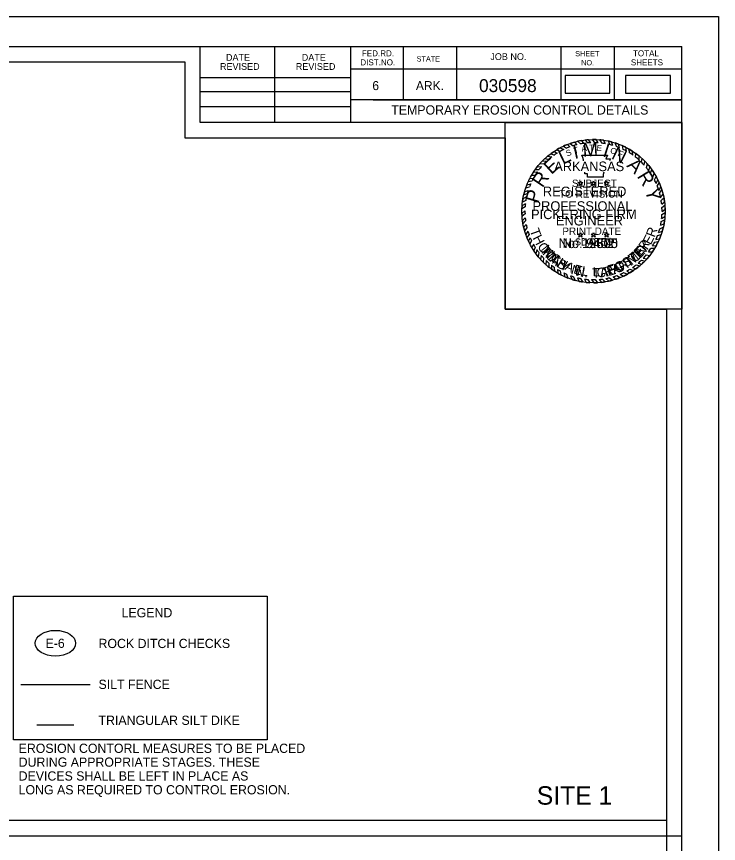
# Model space of a CAD drawing. Extents: x 814841 to 962585, y -174183 to 1802800.
# Drawn here: x 818181 to 818638, y 1802262 to 1802800 of the extents above; entities that cross this region are included whole.
import ezdxf

# ---------------------------------------------------------------- set-up
doc = ezdxf.new("R2010")
doc.units = 0
for name, color, linetype in [('_Silt Dike Legend', 7, 'Continuous'), ('Default', 7, 'Continuous'), ('Legend', 7, 'Continuous'), ('R_Border', 7, 'Continuous'), ('R_Border Notes', 7, 'Continuous'), ('R_Border Plan-Plan', 7, 'Continuous'), ('R_No Plot', 7, 'Continuous'), ('STAMP_PE_CRAFTON', 7, 'Continuous'), ('STAMP_PE_FOSTER', 7, 'Continuous'), ('STAMP_PE_SEAL-INFO', 7, 'Continuous'), ('STAMP_PE_TAEGTMEYER', 7, 'Continuous'), ('STAMP_PE_TXT', 7, 'Continuous'), ('STAMP_PRELIMINARY', 7, 'Continuous'), ('Veg Buffer', 7, 'Continuous')]:
    doc.layers.add(name, color=color, linetype=linetype)

# ---------------------------------------------------------------- blocks, each defined once
blk = doc.blocks.new('E-6')
at = {"layer": 'Default'}
blk.add_ellipse((0, 0), major_axis=(13.15, 0), ratio=0.638788, dxfattribs=at)
blk.add_text('E-6', height=6, dxfattribs=at).set_placement((-6.43, -3))

msp = doc.modelspace()

# ---------------------------------------------------------------- linework, layer by layer
at = {"layer": '_Silt Dike Legend'}
msp.add_line((818194.5, 1802339.12), (818218.5, 1802339.12), dxfattribs=at)
at = {"layer": 'Legend'}
msp.add_line((818184.07, 1802365.5), (818229.09, 1802365.5), dxfattribs=at)
msp.add_lwpolyline([(818179.3, 1802422.91), (818344.3, 1802422.91), (818344.3, 1802329.38), (818179.3, 1802329.38)], close=True, dxfattribs=at)
at = {"layer": 'R_Border'}
for p, q in [((817033.1, 1802780.6), (818614, 1802780.6)), ((818300.8, 1802731.2), (818300.8, 1802780.6)), ((818349.2, 1802731.2), (818349.2, 1802780.6)), ((818398.5, 1802780.6), (818398.5, 1802731.2)), ((818432.7, 1802780.6), (818432.7, 1802745.9)), ((818467.4, 1802780.6), (818467.4, 1802745.9)), ((818535.3, 1802780.6), (818535.3, 1802745.9)), ((818570, 1802780.6), (818570, 1802745.9)), ((818614, 1801753.3), (818614, 1802780.6)), ((818614, 1802765.9), (818398.5, 1802765.9)), ((818614, 1802766), (818614, 1802766)), ((818300.8, 1802760.5), (818398.5, 1802760.5)), ((818300.8, 1802751.2), (818398.5, 1802751.2)), ((818614, 1802745.9), (818398.5, 1802745.9)), ((818413.3, 1802745.9), (818614, 1802745.9)), ((818300.8, 1802741.5), (818398.5, 1802741.5)), ((818614, 1802731.2), (818300.8, 1802731.2))]:
    msp.add_line(p, q, dxfattribs=at)
at = {"layer": 'R_Border Plan-Plan'}
msp.add_line((817033.1, 1802266.95), (818614, 1802266.95), dxfattribs=at)
at = {"layer": 'R_No Plot'}
for points in [[(816971.06, 1802800.08), (818637.76, 1802800.08), (818637.76, 1801733.39), (816971.06, 1801733.39)], [(818604, 1802276.95), (817043.1, 1802276.95), (817043.1, 1802770.6), (818290.8, 1802770.6), (818290.8, 1802721.2), (818378.5, 1802721.2), (818499, 1802721.2), (818499, 1802609.54), (818604, 1802609.54)], [(818604, 1802276.95), (817043.1, 1802276.95), (817043.1, 1802770.6), (818290.8, 1802770.6), (818290.8, 1802721.2), (818378.5, 1802721.2), (818499, 1802721.2), (818499, 1802609.54), (818604, 1802609.54)], [(818604, 1802276.95), (817043.1, 1802276.95), (817043.1, 1802770.6), (818290.8, 1802770.6), (818290.8, 1802721.2), (818378.5, 1802721.2), (818499, 1802721.2), (818499, 1802609.54), (818604, 1802609.54)], [(818604, 1802276.95), (817043.1, 1802276.95), (817043.1, 1802770.6), (818290.8, 1802770.6), (818290.8, 1802721.2), (818378.5, 1802721.2), (818499, 1802721.2), (818499, 1802609.54), (818604, 1802609.54)], [(818604, 1802276.95), (817043.1, 1802276.95), (817043.1, 1802770.6), (818290.8, 1802770.6), (818290.8, 1802721.2), (818378.5, 1802721.2), (818499, 1802721.2), (818499, 1802609.54), (818604, 1802609.54)], [(818604, 1802276.95), (817043.1, 1802276.95), (817043.1, 1802770.6), (818290.8, 1802770.6), (818290.8, 1802721.2), (818378.5, 1802721.2), (818499, 1802721.2), (818499, 1802609.54), (818604, 1802609.54)], [(817043.1, 1802770.6), (818290.8, 1802770.6), (818290.8, 1802721.2), (818378.5, 1802721.2), (818499, 1802721.2), (818499, 1802609.54), (818604, 1802609.54), (818604, 1801763.3), (817043.1, 1801763.3)], [(818604, 1802276.95), (817043.1, 1802276.95), (817043.1, 1802770.6), (818290.8, 1802770.6), (818290.8, 1802721.2), (818378.5, 1802721.2), (818499, 1802721.2), (818499, 1802609.54), (818604, 1802609.54)], [(818499, 1802731.2), (818614, 1802731.2), (818614, 1802609.54), (818499, 1802609.54)]]:
    msp.add_lwpolyline(points, close=True, dxfattribs=at)
at = {"layer": 'STAMP_PE_SEAL-INFO'}
for p, q in [((818546.19, 1802718.88), (818547.97, 1802717.16)), ((818548.6, 1802719.36), (818550.1, 1802717.52)), ((818551.18, 1802719.72), (818552.59, 1802717.81)), ((818554.86, 1802717.95), (818553.3, 1802719.92)), ((818557.35, 1802717.98), (818555.95, 1802720.03)), ((818559.64, 1802717.87), (818558.35, 1802719.99)), ((818562.17, 1802717.62), (818560.71, 1802719.84)), ((818564.29, 1802717.3), (818563.01, 1802719.57)), ((818567.11, 1802716.7), (818566.24, 1802719)), ((818569.11, 1802716.16), (818568.32, 1802718.51)), ((818532.62, 1802713.45), (818534.79, 1802712.34)), ((818534.86, 1802714.7), (818537.18, 1802713.58)), ((818537.02, 1802715.76), (818538.97, 1802714.39)), ((818539.56, 1802716.84), (818541.03, 1802715.21)), ((818541.3, 1802717.48), (818543.2, 1802715.95)), ((818544.25, 1802718.39), (818545.69, 1802716.65)), ((818571.37, 1802715.43), (818570.67, 1802717.82)), ((818573.46, 1802714.63), (818572.74, 1802717.11)), ((818575.77, 1802713.6), (818575.26, 1802716.09)), ((818578, 1802712.45), (818577.57, 1802715)), ((818579.94, 1802711.32), (818579.74, 1802713.82)), ((818524.99, 1802707.76), (818527.28, 1802707.07)), ((818526.7, 1802709.26), (818529.35, 1802708.76)), ((818528.59, 1802710.9), (818530.87, 1802709.87)), ((818530.69, 1802712.23), (818532.9, 1802711.22)), ((818548.86, 1802709.87), (818565.58, 1802709.87)), ((818549.47, 1802708.34), (818548.86, 1802709.87)), ((818549.99, 1802706.85), (818549.47, 1802708.34)), ((818565.58, 1802709.87), (818564.46, 1802707.41)), ((818582.11, 1802709.89), (818581.96, 1802712.46)), ((818583.91, 1802708.55), (818584.08, 1802710.99)), ((818586.15, 1802706.69), (818586.24, 1802709.31)), ((818587.71, 1802705.23), (818588.06, 1802707.72)), ((818519.97, 1802702.37), (818522.71, 1802702.48)), ((818521.69, 1802704.42), (818524.3, 1802704.23)), ((818523.31, 1802706.14), (818526.03, 1802705.94)), ((818550.03, 1802706.28), (818549.99, 1802706.85)), ((818564.46, 1802707.41), (818567.62, 1802707.41)), ((818567.62, 1802707.41), (818566.9, 1802706.28)), ((818589.5, 1802703.36), (818589.84, 1802705.99)), ((818590.87, 1802701.78), (818591.56, 1802704.14)), ((818516.17, 1802696.79), (818518.62, 1802696.89)), ((818517.4, 1802698.8), (818519.98, 1802698.97)), ((818518.58, 1802700.52), (818521.1, 1802700.49)), ((818550.98, 1802697.73), (818550.85, 1802698.82)), ((818552.55, 1802697.73), (818550.98, 1802697.73)), ((818552.55, 1802695.58), (818552.55, 1802697.73)), ((818562.78, 1802697.27), (818562.7, 1802695.58)), ((818563.17, 1802698.82), (818562.78, 1802697.27)), ((818592.49, 1802699.7), (818593.17, 1802702.19)), ((818593.59, 1802698.12), (818594.48, 1802700.44)), ((818595.13, 1802695.63), (818596.05, 1802698.09)), ((818514.08, 1802692.73), (818516.59, 1802693.25)), ((818515.02, 1802694.68), (818517.51, 1802695)), ((818562.7, 1802695.58), (818552.55, 1802695.58)), ((818596.13, 1802693.8), (818597.26, 1802696.02)), ((818597.29, 1802691.38), (818598.42, 1802693.81)), ((818597.99, 1802689.7), (818599.31, 1802691.86)), ((818511.62, 1802686.02), (818514.01, 1802686.87)), ((818512.41, 1802688.54), (818514.83, 1802689.22)), ((818513.16, 1802690.57), (818515.68, 1802691.3)), ((818598.96, 1802686.95), (818600.31, 1802689.32)), ((818599.5, 1802685.13), (818600.97, 1802687.39)), ((818512.92, 1802682.75), (818510.59, 1802681.51)), ((818511.1, 1802683.99), (818513.45, 1802684.95)), ((818600.17, 1802682.33), (818601.76, 1802684.57)), ((818600.51, 1802680.43), (818602.28, 1802682.2)), ((818512.02, 1802676.16), (818509.91, 1802674.87)), ((818512.2, 1802678.28), (818510.01, 1802676.88)), ((818512.49, 1802680.46), (818510.27, 1802679.35)), ((818600.84, 1802677.89), (818602.71, 1802679.57)), ((818601, 1802675.8), (818602.95, 1802677.26)), ((818511.93, 1802673.69), (818509.91, 1802672.01)), ((818511.97, 1802671.66), (818510.01, 1802670.03)), ((818601.01, 1802671.18), (818603.11, 1802672.57)), ((818601.07, 1802673.21), (818603.09, 1802674.82)), ((818512.13, 1802669.18), (818510.28, 1802667.4)), ((818512.39, 1802667.03), (818510.62, 1802665.17)), ((818512.78, 1802664.74), (818511.09, 1802662.9)), ((818600.11, 1802664.21), (818602.38, 1802665.19)), ((818600.56, 1802666.71), (818602.77, 1802667.81)), ((818600.81, 1802668.65), (818602.98, 1802669.93)), ((818513.25, 1802662.64), (818511.69, 1802660.57)), ((818513.87, 1802660.41), (818512.4, 1802658.32)), ((818598.83, 1802659.48), (818601.28, 1802660.48)), ((818599.57, 1802661.95), (818601.92, 1802662.96)), ((818514.58, 1802658.29), (818513.17, 1802656.23)), ((818515.41, 1802656.16), (818514.1, 1802654.05)), ((818516.27, 1802654.24), (818515.13, 1802651.94)), ((818597.09, 1802655.01), (818599.53, 1802655.49)), ((818598.16, 1802657.58), (818600.57, 1802658.23)), ((818517.44, 1802651.95), (818516.49, 1802649.5)), ((818518.62, 1802649.93), (818517.7, 1802647.58)), ((818594.06, 1802649.43), (818596.45, 1802649.4)), ((818594.92, 1802650.83), (818597.43, 1802651.1)), ((818596.28, 1802653.33), (818598.72, 1802653.67)), ((818519.63, 1802648.38), (818519.08, 1802645.62)), ((818521.04, 1802646.42), (818520.53, 1802643.77)), ((818522.56, 1802644.54), (818522.12, 1802641.94)), ((818590.83, 1802644.99), (818593.13, 1802644.59)), ((818592.36, 1802646.96), (818594.89, 1802646.97)), ((818524.07, 1802642.85), (818523.76, 1802640.24)), ((818525.68, 1802641.22), (818525.53, 1802638.58)), ((818527.4, 1802639.66), (818527.39, 1802637.01)), ((818529.2, 1802638.19), (818529.3, 1802635.56)), ((818584.25, 1802638.54), (818586.59, 1802637.82)), ((818585.61, 1802639.67), (818587.96, 1802639.02)), ((818587.64, 1802641.53), (818589.84, 1802640.84)), ((818588.91, 1802642.82), (818591.29, 1802642.4)), ((818530.89, 1802636.94), (818531.07, 1802634.35)), ((818533.03, 1802635.53), (818533.33, 1802632.97)), ((818534.78, 1802634.5), (818535.24, 1802631.93)), ((818537.19, 1802633.25), (818537.97, 1802630.64)), ((818539.05, 1802632.41), (818539.91, 1802629.85)), ((818573.82, 1802632.35), (818575.94, 1802631.05)), ((818576.12, 1802633.4), (818578.54, 1802632.34)), ((818578.16, 1802634.47), (818580.24, 1802633.3)), ((818580.23, 1802635.69), (818582.48, 1802634.71)), ((818581.95, 1802636.83), (818584.14, 1802635.88)), ((818541.51, 1802631.44), (818542.56, 1802628.94)), ((818543.56, 1802630.77), (818544.69, 1802628.32)), ((818546.1, 1802630.08), (818547.16, 1802627.75)), ((818548.09, 1802629.65), (818549.32, 1802627.36)), ((818550.59, 1802629.24), (818551.79, 1802627.04)), ((818552.77, 1802629), (818554.14, 1802626.86)), ((818555.19, 1802628.87), (818556.71, 1802626.8)), ((818557.49, 1802628.86), (818559.21, 1802626.88)), ((818560.09, 1802628.99), (818561.71, 1802627.09)), ((818562.28, 1802629.22), (818564.14, 1802627.43)), ((818564.5, 1802629.57), (818566.45, 1802627.88)), ((818566.97, 1802630.09), (818568.85, 1802628.47)), ((818569.26, 1802630.72), (818571.34, 1802629.23)), ((818571.73, 1802631.53), (818573.94, 1802630.19))]:
    msp.add_line(p, q, dxfattribs=at)
for radius, start, end in [(46.61, 99.7525, 102.7765), (46.61, 93.9381, 96.5517), (46.61, 87.7298, 90.6707), (46.61, 81.9732, 84.8236), (46.61, 75.3125, 77.9426), (46.61, 117.6544, 120.8099), (44.57, 115.6869, 119.1583), (46.61, 111.3124, 114.7026), (44.57, 110.3086, 113.1659), (46.61, 105.2339, 109.0352), (44.57, 104.0352, 107.3615), (44.57, 98.258, 101.0329), (44.57, 92.1102, 95.0367), (44.57, 85.9628, 88.9097), (44.57, 79.9264, 82.696), (44.57, 73.5575, 76.2314), (46.61, 69.6061, 72.3058), (44.57, 67.6248, 70.504), (46.61, 63.1329, 66.2704), (44.57, 61.1558, 64.3784), (46.61, 56.9003, 60.0942), (46.61, 129.7326, 132.5376), (44.57, 127.5297, 130.9683), (46.61, 123.6199, 126.5906), (44.57, 121.9746, 125.11), (44.57, 54.9238, 58.2702), (44.57, 48.3016, 52.0395), (46.61, 50.3492, 53.7159), (46.61, 44.3405, 47.3929), (46.61, 141.6056, 144.4486), (44.57, 139.301, 142.5873), (46.61, 135.4021, 138.3031), (44.57, 133.1331, 136.2562), (44.57, 42.2212, 45.5512), (46.61, 38.1247, 41.2316), (46.61, 147.0072, 149.899), (44.57, 145.0197, 148.2104), (44.57, 36.135, 39.5311), (44.57, 29.9032, 33.6645), (46.61, 31.9614, 35.4294), (46.61, 152.864, 155.5189), (44.57, 151.0315, 153.573), (44.57, 23.7732, 27.2211), (46.61, 25.9391, 29.0125), (46.61, 19.9538, 23.3141), (46.61, 158.4077, 161.0701), (44.57, 162.4331, 165.0013), (44.57, 156.3402, 159.2319), (44.57, 17.6802, 21.4251), (46.61, 13.8421, 17.4447), (46.61, 170.0003, 172.6878), (46.61, 164.3068, 166.894), (44.57, 167.9048, 170.9039), (44.57, 11.5444, 15.2364), (46.61, 7.5852, 10.8621), (46.61, 175.7409, 178.2066), (44.57, 173.73, 176.4734), (44.57, 5.7599, 9.0606), (44.57, 359.7329, 3.0639), (46.61, 1.7215, 4.7268), (46.61, 181.7251, 184.1626), (44.57, 179.6454, 182.2633), (44.57, 353.8632, 357.1274), (46.61, 355.7156, 358.9569), (46.61, 187.4204, 190.1927), (44.57, 185.4539, 188.234), (44.57, 191.2274, 193.9858), (44.57, 348.0778, 351.3435), (46.61, 349.8305, 353.0885), (46.61, 193.0369, 195.9973), (44.57, 196.9675, 199.8353), (44.57, 341.777, 345.0925), (46.61, 343.8925, 347.035), (46.61, 198.8967, 201.6281), (46.61, 204.5479, 207.4328), (44.57, 202.7761, 205.4791), (44.57, 335.6038, 339.1858), (46.61, 337.3837, 340.9933), (46.61, 210.8636, 213.6571), (44.57, 208.7883, 211.7934), (44.57, 323.5851, 327.4407), (46.61, 325.4405, 328.9872), (44.57, 329.5549, 333.2076), (46.61, 331.4037, 334.9332), (46.61, 216.6115, 219.491), (44.57, 214.1838, 217.2747), (44.57, 220.3909, 223.3056), (44.57, 316.6531, 320.3711), (46.61, 318.2846, 321.8043), (46.61, 222.48, 225.3801), (46.61, 228.3665, 231.348), (44.57, 226.2494, 229.2407), (44.57, 232.229, 234.9336), (44.57, 304.823, 308.5143), (46.61, 306.3721, 310.208), (44.57, 310.7744, 314.3161), (46.61, 312.4518, 315.6633), (46.61, 234.295, 236.9452), (44.57, 238.2223, 240.8353), (46.61, 240.1977, 242.8613), (44.57, 244.3204, 246.9486), (44.57, 292.8745, 296.1185), (46.61, 294.6481, 298.2166), (44.57, 299.0768, 302.1724), (46.61, 300.621, 303.8703), (46.61, 246.576, 249.1558), (44.57, 250.3491, 253.1216), (46.61, 252.5967, 255.3252), (44.57, 256.505, 259.1192), (46.61, 258.4433, 261.1398), (44.57, 262.3783, 265.2012), (46.61, 264.1978, 267.1009), (44.57, 268.3215, 271.277), (44.57, 274.6157, 277.4486), (46.61, 276.4239, 279.4357), (44.57, 280.3459, 283.5814), (46.61, 282.3199, 285.3702), (44.57, 286.6423, 289.9783), (46.61, 288.5709, 291.9733), (46.61, 270.2548, 273.3361)]:
    msp.add_arc((818556.5, 1802673.42), radius, start, end, dxfattribs=at)
at = {"layer": 'STAMP_PE_TXT'}
for p, q in [((818547.4, 1802691.27), (818546.4, 1802691.99)), ((818546.4, 1802691.99), (818547.63, 1802691.99)), ((818547.63, 1802691.99), (818548.01, 1802693.16)), ((818548.01, 1802693.16), (818548.39, 1802691.99)), ((818548.39, 1802691.99), (818549.61, 1802691.99)), ((818549.61, 1802691.99), (818548.62, 1802691.27)), ((818555.89, 1802691.27), (818554.89, 1802691.99)), ((818554.89, 1802691.99), (818556.12, 1802691.99)), ((818556.12, 1802691.99), (818556.5, 1802693.16)), ((818556.5, 1802693.16), (818556.88, 1802691.99)), ((818556.88, 1802691.99), (818558.1, 1802691.99)), ((818558.1, 1802691.99), (818557.11, 1802691.27)), ((818564.38, 1802691.27), (818563.38, 1802691.99)), ((818563.38, 1802691.99), (818564.61, 1802691.99)), ((818564.61, 1802691.99), (818564.99, 1802693.16)), ((818564.99, 1802693.16), (818565.37, 1802691.99)), ((818565.37, 1802691.99), (818566.59, 1802691.99)), ((818566.59, 1802691.99), (818565.6, 1802691.27)), ((818547.02, 1802690.11), (818547.4, 1802691.27)), ((818548.01, 1802690.83), (818547.02, 1802690.11)), ((818549, 1802690.11), (818548.01, 1802690.83)), ((818548.62, 1802691.27), (818549, 1802690.11)), ((818555.51, 1802690.11), (818555.89, 1802691.27)), ((818556.5, 1802690.83), (818555.51, 1802690.11)), ((818557.49, 1802690.11), (818556.5, 1802690.83)), ((818557.11, 1802691.27), (818557.49, 1802690.11)), ((818564, 1802690.11), (818564.38, 1802691.27)), ((818564.99, 1802690.83), (818564, 1802690.11)), ((818565.98, 1802690.11), (818564.99, 1802690.83)), ((818565.6, 1802691.27), (818565.98, 1802690.11)), ((818547.63, 1802658.46), (818548.01, 1802659.62)), ((818548.01, 1802659.62), (818548.39, 1802658.46)), ((818556.12, 1802658.46), (818556.5, 1802659.62)), ((818556.5, 1802659.62), (818556.88, 1802658.46)), ((818564.61, 1802658.46), (818564.99, 1802659.62)), ((818564.99, 1802659.62), (818565.37, 1802658.46)), ((818547.4, 1802657.74), (818546.4, 1802658.46)), ((818546.4, 1802658.46), (818547.63, 1802658.46)), ((818547.02, 1802656.57), (818547.4, 1802657.74)), ((818548.01, 1802657.29), (818547.02, 1802656.57)), ((818549, 1802656.57), (818548.01, 1802657.29)), ((818548.39, 1802658.46), (818549.61, 1802658.46)), ((818549.61, 1802658.46), (818548.62, 1802657.74)), ((818548.62, 1802657.74), (818549, 1802656.57)), ((818555.89, 1802657.74), (818554.89, 1802658.46)), ((818554.89, 1802658.46), (818556.12, 1802658.46)), ((818555.51, 1802656.57), (818555.89, 1802657.74)), ((818556.5, 1802657.29), (818555.51, 1802656.57)), ((818557.49, 1802656.57), (818556.5, 1802657.29)), ((818556.88, 1802658.46), (818558.1, 1802658.46)), ((818558.1, 1802658.46), (818557.11, 1802657.74)), ((818557.11, 1802657.74), (818557.49, 1802656.57)), ((818564.38, 1802657.74), (818563.38, 1802658.46)), ((818563.38, 1802658.46), (818564.61, 1802658.46)), ((818564, 1802656.57), (818564.38, 1802657.74)), ((818564.99, 1802657.29), (818564, 1802656.57)), ((818565.98, 1802656.57), (818564.99, 1802657.29)), ((818565.37, 1802658.46), (818566.59, 1802658.46)), ((818566.59, 1802658.46), (818565.6, 1802657.74)), ((818565.6, 1802657.74), (818565.98, 1802656.57))]:
    msp.add_line(p, q, dxfattribs=at)
at = {"layer": 'STAMP_PRELIMINARY'}
msp.add_circle((818556.5, 1802673.42), 46.61, dxfattribs=at)
at = {"layer": 'Veg Buffer'}
for points in [[(818538.07, 1802750.13), (818567.23, 1802750.13), (818567.23, 1802761.68), (818538.07, 1802761.68)], [(818577.42, 1802750.13), (818606.58, 1802750.13), (818606.58, 1802761.68), (818577.42, 1802761.68)]]:
    msp.add_lwpolyline(points, close=True, dxfattribs=at)

# ---------------------------------------------------------------- block references
at = {"layer": 'Legend', "rotation": -1.8065126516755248e-10}
msp.add_blockref('E-6', (818206.58, 1802392.22), dxfattribs=at)

# ---------------------------------------------------------------- texts
at = {"layer": 'Legend'}
for s, p in [('LEGEND', (818249.62, 1802409.12)), ('ROCK DITCH CHECKS', (818234.62, 1802389.12)), ('SILT FENCE', (818234.62, 1802362.5)), ('TRIANGULAR SILT DIKE', (818234.62, 1802339.12)), ('EROSION CONTORL MEASURES TO BE PLACED', (818182.68, 1802320.89)), ('DURING APPROPRIATE STAGES. THESE ', (818182.68, 1802311.89)), ('DEVICES SHALL BE LEFT IN PLACE AS ', (818182.68, 1802302.89)), ('LONG AS REQUIRED TO CONTROL EROSION.', (818182.68, 1802293.89))]:
    msp.add_text(s, height=6, dxfattribs=at).set_placement(p)
at = {"layer": 'R_Border'}
for s, height, p in [('FED.RD.', 3.91, (818405.9, 1802774.2)), ('SHEET', 3.42, (818544.6, 1802774.2)), ('TOTAL', 3.91, (818582.2, 1802774.2)), ('DATE', 4.396, (818317.49, 1802771.28)), ('DATE', 4.396, (818366.79, 1802771.28)), ('DIST.NO.', 3.91, (818404.9, 1802768.3)), ('STATE', 3.42, (818441.5, 1802770.8)), ('JOB NO.', 4.396, (818489.4, 1802771.8)), ('SHEETS', 3.91, (818580.8, 1802768.3)), ('REVISED', 4.396, (818313.59, 1802765.38)), ('REVISED', 4.396, (818362.89, 1802765.38)), ('NO.', 3.42, (818548.5, 1802768.3)), ('6', 5.86, (818412.7, 1802752.2)), ('ARK.', 5.861, (818441, 1802752.2)), ('SITE 1', 12, (818519.64, 1802287.19))]:
    msp.add_text(s, height=height, dxfattribs=at).set_placement(p)
at = {"layer": 'R_Border Notes'}
for s, height, p in [('030598', 8.4, (818482.06, 1802750.93)), ('TEMPORARY EROSION CONTROL DETAILS', 6, (818425, 1802736.3))]:
    msp.add_text(s, height=height, dxfattribs=at).set_placement(p)
at = {"layer": 'STAMP_PE_CRAFTON'}
msp.add_text('No. 12370', height=6.25, dxfattribs=at).set_placement((818533.81, 1802649.4))
for s, rotation, p in [('T', 310.7442, (818521.33, 1802647.9)), ('N', 49.2411, (818587.91, 1802643.53)), ('O', 317.6422, (818524.67, 1802643.85)), ('N', 324.4537, (818528.89, 1802639.92)), ('T', 34.1136, (818579.38, 1802636.61)), ('O', 41.8391, (818583.67, 1802639.62)), ('Y', 331.1686, (818534.06, 1802636.34)), ('N', 347.4752, (818544.33, 1802631.76)), ('R', 14.8189, (818564.34, 1802630.7)), ('A', 20.5125, (818569.9, 1802632.19)), ('F', 28.7821, (818574.81, 1802634.06)), ('C', 6.0117, (818558.86, 1802630.12)), ('.', 356.8926, (818550.48, 1802630.38))]:
    msp.add_text(s, height=6.25, rotation=rotation, dxfattribs=at).set_placement(p)
at = {"layer": 'STAMP_PE_FOSTER'}
msp.add_text('No. 9402', height=6.25, dxfattribs=at).set_placement((818536.43, 1802649.4))
for s, rotation, p in [('R', 54.5031, (818590.12, 1802647.47)), ('M', 308.339, (818522.08, 1802648.53)), ('E', 46.9613, (818586.5, 1802643.37)), ('I', 314.1842, (818526.07, 1802643.84)), ('C', 319.8733, (818527.84, 1802642.07)), ('H', 327.7235, (818532.48, 1802638.39)), ('S', 31.7234, (818577.45, 1802636.48)), ('T', 39.4194, (818582.21, 1802639.62)), ('A', 335.7276, (818537.39, 1802635.48)), ('E', 343.5779, (818543.08, 1802633.13)), ('F', 15.8691, (818566.67, 1802632.19)), ('O', 23.719, (818571.9, 1802633.83)), ('L', 350.8115, (818548.37, 1802631.74)), ('L', 1.2666, (818556.07, 1802630.96)), ('.', 6.8035, (818561.3, 1802631.25))]:
    msp.add_text(s, height=6, rotation=rotation, dxfattribs=at).set_placement(p)
at = {"layer": 'STAMP_PE_TAEGTMEYER'}
for s, rotation, p in [('T', 289.646, (818514.97, 1802660.97)), ('R', 69.57, (818596.22, 1802655.99)), ('H', 296.7339, (818516.77, 1802656.04)), ('Y', 53.9986, (818590.39, 1802646.38)), ('E', 63.0984, (818593.73, 1802651.08)), ('O', 303.7708, (818519.74, 1802650.5)), ('M', 314.2033, (818523.01, 1802645.75)), ('E', 46.8094, (818586.69, 1802642.3)), ('A', 321.0594, (818527.82, 1802640.93)), ('T', 31.466, (818577, 1802635.19)), ('M', 39.3, (818581.49, 1802637.91)), ('S', 327.8239, (818531.95, 1802637.71)), ('N', 344.2727, (818541.43, 1802632.67)), ('E', 17.6836, (818566.25, 1802631.07)), ('G', 23.3052, (818571.5, 1802632.73)), ('T', 3.0061, (818555.82, 1802630.02)), ('A', 8.9826, (818561.05, 1802630.3)), ('.', 350.6464, (818547.5, 1802631.01))]:
    msp.add_text(s, height=6.25, rotation=rotation, dxfattribs=at).set_placement(p)
msp.add_text('No. 19605', height=6.25, dxfattribs=at).set_placement((818533.81, 1802649.4))
at = {"layer": 'STAMP_PE_TXT'}
for s, rotation, p in [('S', 23.5541, (818539.49, 1802708.93)), ('T', 16.311, (818544.11, 1802710.8)), ('A', 9.0679, (818548.92, 1802712.06)), ('T', 1.8248, (818553.85, 1802712.71)), ('E', 355.2002, (818558.4, 1802712.75)), ('O', 342.2506, (818567.04, 1802711.37)), ('F', 335.0075, (818571.86, 1802709.68))]:
    msp.add_text(s, height=3.91, rotation=rotation, dxfattribs=at).set_placement(p)
for s, p in [('ARKANSAS', (818530.96, 1802699.47)), ('REGISTERED', (818523.58, 1802683.12)), ('PROFESSIONAL', (818516.84, 1802673.61)), ('ENGINEER', (818532.04, 1802664.11))]:
    msp.add_text(s, height=6.25, dxfattribs=at).set_placement(p)
at = {"layer": 'STAMP_PRELIMINARY'}
for s, rotation, p in [('I', 12.5248, (818544.19, 1802707.35)), ('M', 3.1074, (818549.68, 1802708.89)), ('I', 342.3164, (818562.02, 1802709.23)), ('N', 333.9382, (818567.55, 1802707.86)), ('E', 42.3578, (818529.13, 1802696.9)), ('L', 25.513, (818536.54, 1802703.55)), ('A', 315.6579, (818577.72, 1802702.73)), ('R', 56.2292, (818523.35, 1802688.23)), ('R', 301.3831, (818584.56, 1802696.16)), ('P', 73.913, (818520.61, 1802678.12)), ('Y', 283.2593, (818590.01, 1802687.23))]:
    msp.add_text(s, height=9, rotation=rotation, dxfattribs=at).set_placement(p)
for s, height, p in [('SUBJECT', 4.8, (818542.5, 1802689.16)), ('TO REVISION', 4.8, (818534.18, 1802682.24)), ('PICKERING FIRM', 6.25, (818515.87, 1802668.23)), ('PRINT DATE', 4.8, (818536.29, 1802657.99)), ('$DATE$', 4.8, (818544.67, 1802651.07))]:
    msp.add_text(s, height=height, dxfattribs=at).set_placement(p)

doc.saveas('drawing.dxf')
